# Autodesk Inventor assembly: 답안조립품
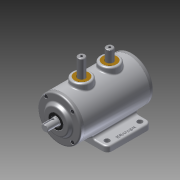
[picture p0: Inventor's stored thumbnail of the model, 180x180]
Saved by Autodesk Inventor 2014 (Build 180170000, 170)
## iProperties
Created: 2014-12
Part Number: 답안조립품
Document SubType Name: Assembly
Designer: Owner
Author: Owner
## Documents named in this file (10)
- C:\Users\Owner\Desktop\441223V1023\답안조립품.iam
- C:\Users\Owner\Desktop\441223V1023\본체.ipt
- C:\Users\Owner\Desktop\441223V1023\M4-소켓머리.ipt
- C:\Users\Owner\Desktop\441223V1023\뒷커버.ipt
- C:\Users\Owner\Desktop\441223V1023\베어링 6203.ipt
- C:\Users\Owner\Desktop\441223V1023\부시.ipt
- C:\Users\Owner\Desktop\441223V1023\슬라이더.ipt
- C:\Users\Owner\Desktop\441223V1023\앞커버.ipt
- C:\Users\Owner\Desktop\441223V1023\오일실.ipt
- C:\Users\Owner\Desktop\441223V1023\축.ipt
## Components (11 placed, 3 different names)
1. 7-베어링 6203:1
2. 8-오일실:1
3. 7-베어링 6203:2
4. 9-M4-소켓머리:1
5. 9-M4-소켓머리:3
6. 9-M4-소켓머리:4
7. 9-M4-소켓머리:5
8. 9-M4-소켓머리:2
9. 9-M4-소켓머리:6
10. 9-M4-소켓머리:7
11. 9-M4-소켓머리:8
